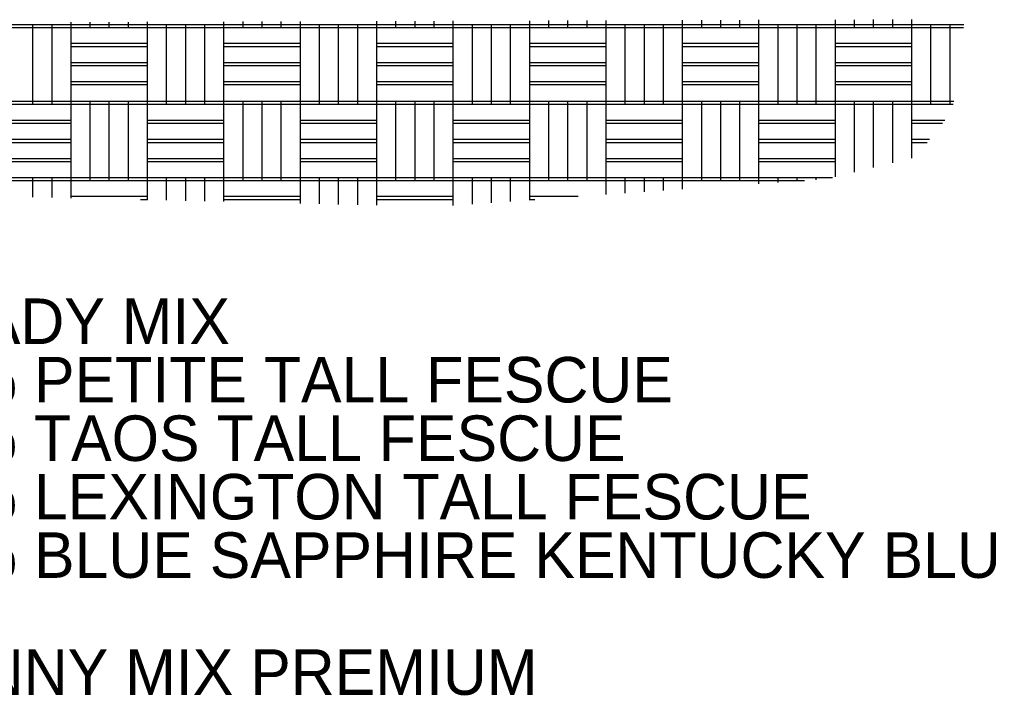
# Model space of a CAD drawing. Extents: x 9966.4 to 10027.9, y 9879.4 to 9942.8.
# Drawn here: x 9984.77 to 10007.1, y 9911.19 to 9926.69 of the extents above; entities that cross this region are included whole.
import ezdxf

# ---------------------------------------------------------------- set-up
doc = ezdxf.new("R2010")
doc.units = 0
for name, color, linetype in [('Default', 7, 'Continuous'), ('G-ANNO-TEXT', 7, 'Continuous'), ('G-DETL-PATT', 7, 'Continuous')]:
    doc.layers.add(name, color=color, linetype=linetype)

msp = doc.modelspace()

# ---------------------------------------------------------------- linework, layer by layer
at = {"layer": 'Default'}
for p, q in [((9998.232, 9926.139), (9996.478, 9926.139)), ((10001.74, 9926.139), (9999.986, 9926.139)), ((10005.248, 9926.139), (10003.494, 9926.139)), ((9996.598, 9922.561), (9996.478, 9922.561))]:
    msp.add_line(p, q, dxfattribs=at)
at = {"layer": 'G-DETL-PATT'}
for p, q in [((9979.4, 9926.578), (10006.438, 9926.578)), ((9985.078, 9924.824), (9985.078, 9926.578)), ((9985.516, 9924.824), (9985.516, 9926.578)), ((9985.954, 9926.578), (9985.954, 9926.631)), ((9985.954, 9926.507), (9985.954, 9926.631)), ((9985.954, 9924.824), (9985.954, 9926.578)), ((9986.393, 9926.578), (9986.393, 9926.632)), ((9986.393, 9926.507), (9986.393, 9926.632)), ((9986.831, 9926.578), (9986.831, 9926.634)), ((9986.831, 9926.507), (9986.831, 9926.634)), ((9987.27, 9926.578), (9987.27, 9926.635)), ((9987.27, 9926.507), (9987.27, 9926.635)), ((9987.708, 9926.578), (9987.708, 9926.637)), ((9987.708, 9926.507), (9987.708, 9926.637)), ((9987.708, 9924.824), (9987.708, 9926.578)), ((9988.147, 9924.824), (9988.147, 9926.578)), ((9988.585, 9924.824), (9988.585, 9926.578)), ((9989.024, 9924.824), (9989.024, 9926.578)), ((9989.462, 9926.578), (9989.462, 9926.642)), ((9989.462, 9926.507), (9989.462, 9926.642)), ((9989.462, 9924.824), (9989.462, 9926.578)), ((9989.901, 9926.578), (9989.901, 9926.644)), ((9989.901, 9926.507), (9989.901, 9926.644)), ((9990.339, 9926.578), (9990.339, 9926.645)), ((9990.339, 9926.507), (9990.339, 9926.645)), ((9990.778, 9926.578), (9990.778, 9926.647)), ((9990.778, 9926.507), (9990.778, 9926.647)), ((9991.216, 9926.578), (9991.216, 9926.648)), ((9991.216, 9926.507), (9991.216, 9926.648)), ((9991.216, 9924.824), (9991.216, 9926.578)), ((9991.655, 9924.824), (9991.655, 9926.578)), ((9992.093, 9924.824), (9992.093, 9926.578)), ((9992.532, 9924.824), (9992.532, 9926.578)), ((9992.97, 9926.578), (9992.97, 9926.654)), ((9992.97, 9926.507), (9992.97, 9926.654)), ((9992.97, 9924.824), (9992.97, 9926.578)), ((9993.409, 9926.578), (9993.409, 9926.655)), ((9993.409, 9926.507), (9993.409, 9926.655)), ((9993.847, 9926.578), (9993.847, 9926.656)), ((9993.847, 9926.507), (9993.847, 9926.656)), ((9994.286, 9926.578), (9994.286, 9926.658)), ((9994.286, 9926.507), (9994.286, 9926.658)), ((9994.724, 9926.578), (9994.724, 9926.659)), ((9994.724, 9926.507), (9994.724, 9926.659)), ((9994.724, 9924.824), (9994.724, 9926.578)), ((9995.163, 9924.824), (9995.163, 9926.578)), ((9995.601, 9924.824), (9995.601, 9926.578)), ((9996.04, 9924.824), (9996.04, 9926.578)), ((9996.478, 9926.578), (9996.478, 9926.665)), ((9996.478, 9926.507), (9996.478, 9926.665)), ((9996.478, 9924.824), (9996.478, 9926.578)), ((9996.917, 9926.578), (9996.917, 9926.667)), ((9996.917, 9926.507), (9996.917, 9926.667)), ((9997.355, 9926.578), (9997.355, 9926.668)), ((9997.355, 9926.507), (9997.355, 9926.668)), ((9997.794, 9926.578), (9997.794, 9926.669)), ((9997.794, 9926.507), (9997.794, 9926.669)), ((9998.232, 9926.578), (9998.232, 9926.671)), ((9998.232, 9926.507), (9998.232, 9926.671)), ((9998.232, 9924.824), (9998.232, 9926.578)), ((9998.671, 9924.824), (9998.671, 9926.578)), ((9999.109, 9924.824), (9999.109, 9926.578)), ((9999.548, 9924.824), (9999.548, 9926.578)), ((9999.986, 9926.578), (9999.986, 9926.676)), ((9999.986, 9926.507), (9999.986, 9926.676)), ((9999.986, 9924.824), (9999.986, 9926.578)), ((10000.425, 9926.578), (10000.425, 9926.678)), ((10000.425, 9926.507), (10000.425, 9926.678)), ((10000.863, 9926.578), (10000.863, 9926.679)), ((10000.863, 9926.507), (10000.863, 9926.679)), ((10001.302, 9926.578), (10001.302, 9926.681)), ((10001.302, 9926.507), (10001.302, 9926.681)), ((10001.74, 9926.578), (10001.74, 9926.682)), ((10001.74, 9926.507), (10001.74, 9926.682)), ((10001.74, 9924.824), (10001.74, 9926.578)), ((10002.179, 9924.824), (10002.179, 9926.578)), ((10002.617, 9924.824), (10002.617, 9926.578)), ((10003.056, 9924.824), (10003.056, 9926.578)), ((10003.494, 9926.578), (10003.494, 9926.688)), ((10003.494, 9926.507), (10003.494, 9926.688)), ((10003.494, 9924.824), (10003.494, 9926.578)), ((10003.933, 9926.578), (10003.933, 9926.689)), ((10003.933, 9926.507), (10003.933, 9926.689)), ((10004.371, 9926.578), (10004.371, 9926.691)), ((10004.371, 9926.507), (10004.371, 9926.691)), ((10004.81, 9926.578), (10004.81, 9926.692)), ((10004.81, 9926.507), (10004.81, 9926.692)), ((10005.248, 9926.578), (10005.248, 9926.694)), ((10005.248, 9926.507), (10005.248, 9926.694)), ((10005.248, 9924.824), (10005.248, 9926.578)), ((10005.687, 9924.824), (10005.687, 9926.578)), ((10006.125, 9924.824), (10006.125, 9926.578)), ((9979.454, 9926.507), (10006.433, 9926.507)), ((9985.078, 9924.753), (9985.078, 9926.507)), ((9985.516, 9924.753), (9985.516, 9926.507)), ((9985.954, 9924.753), (9985.954, 9926.507)), ((9987.708, 9924.753), (9987.708, 9926.507)), ((9988.147, 9924.753), (9988.147, 9926.507)), ((9988.585, 9924.753), (9988.585, 9926.507)), ((9989.024, 9924.753), (9989.024, 9926.507)), ((9989.462, 9924.753), (9989.462, 9926.507)), ((9991.216, 9924.753), (9991.216, 9926.507)), ((9991.655, 9924.753), (9991.655, 9926.507)), ((9992.093, 9924.753), (9992.093, 9926.507)), ((9992.532, 9924.753), (9992.532, 9926.507)), ((9992.97, 9924.753), (9992.97, 9926.507)), ((9994.724, 9924.753), (9994.724, 9926.507)), ((9995.163, 9924.753), (9995.163, 9926.507)), ((9995.601, 9924.753), (9995.601, 9926.507)), ((9996.04, 9924.753), (9996.04, 9926.507)), ((9996.478, 9924.753), (9996.478, 9926.507)), ((9998.232, 9924.753), (9998.232, 9926.507)), ((9998.671, 9924.753), (9998.671, 9926.507)), ((9999.109, 9924.753), (9999.109, 9926.507)), ((9999.548, 9924.753), (9999.548, 9926.507)), ((9999.986, 9924.753), (9999.986, 9926.507)), ((10001.74, 9924.753), (10001.74, 9926.507)), ((10002.179, 9924.753), (10002.179, 9926.507)), ((10002.617, 9924.753), (10002.617, 9926.507)), ((10003.056, 9924.753), (10003.056, 9926.507)), ((10003.494, 9924.753), (10003.494, 9926.507)), ((10005.248, 9924.753), (10005.248, 9926.507)), ((10005.687, 9924.753), (10005.687, 9926.507)), ((10006.125, 9924.753), (10006.125, 9926.507)), ((9987.708, 9926.139), (9985.954, 9926.139)), ((9991.216, 9926.139), (9989.462, 9926.139)), ((9994.724, 9926.139), (9992.97, 9926.139)), ((9987.708, 9926.069), (9985.954, 9926.069)), ((9991.216, 9926.069), (9989.462, 9926.069)), ((9994.724, 9926.069), (9992.97, 9926.069)), ((9998.232, 9926.069), (9996.478, 9926.069)), ((10001.74, 9926.069), (9999.986, 9926.069)), ((10005.248, 9926.069), (10003.494, 9926.069)), ((9987.708, 9925.701), (9985.954, 9925.701)), ((9987.708, 9925.63), (9985.954, 9925.63)), ((9991.216, 9925.701), (9989.462, 9925.701)), ((9991.216, 9925.63), (9989.462, 9925.63)), ((9994.724, 9925.701), (9992.97, 9925.701)), ((9994.724, 9925.63), (9992.97, 9925.63)), ((9998.232, 9925.701), (9996.478, 9925.701)), ((9998.232, 9925.63), (9996.478, 9925.63)), ((10001.74, 9925.701), (9999.986, 9925.701)), ((10001.74, 9925.63), (9999.986, 9925.63)), ((10005.248, 9925.701), (10003.494, 9925.701)), ((10005.248, 9925.63), (10003.494, 9925.63)), ((9987.708, 9925.262), (9985.954, 9925.262)), ((9987.708, 9925.192), (9985.954, 9925.192)), ((9991.216, 9925.262), (9989.462, 9925.262)), ((9991.216, 9925.192), (9989.462, 9925.192)), ((9994.724, 9925.262), (9992.97, 9925.262)), ((9994.724, 9925.192), (9992.97, 9925.192)), ((9998.232, 9925.262), (9996.478, 9925.262)), ((9998.232, 9925.192), (9996.478, 9925.192)), ((10001.74, 9925.262), (9999.986, 9925.262)), ((10001.74, 9925.192), (9999.986, 9925.192)), ((10005.248, 9925.262), (10003.494, 9925.262)), ((10005.248, 9925.192), (10003.494, 9925.192)), ((9980.74, 9924.824), (10006.208, 9924.824)), ((9980.794, 9924.753), (10006.196, 9924.753)), ((9984.201, 9924.824), (9985.954, 9924.824)), ((9984.201, 9924.753), (9985.954, 9924.753)), ((9985.954, 9923.07), (9985.954, 9924.824)), ((9985.954, 9922.999), (9985.954, 9924.753)), ((9986.393, 9923.07), (9986.393, 9924.824)), ((9986.393, 9922.999), (9986.393, 9924.753)), ((9986.831, 9923.07), (9986.831, 9924.824)), ((9986.831, 9922.999), (9986.831, 9924.753)), ((9987.27, 9923.07), (9987.27, 9924.824)), ((9987.27, 9922.999), (9987.27, 9924.753)), ((9987.708, 9923.07), (9987.708, 9924.824)), ((9987.708, 9924.824), (9989.462, 9924.824)), ((9987.708, 9922.999), (9987.708, 9924.753)), ((9987.708, 9924.753), (9989.462, 9924.753)), ((9989.462, 9923.07), (9989.462, 9924.824)), ((9989.462, 9922.999), (9989.462, 9924.753)), ((9989.901, 9923.07), (9989.901, 9924.824)), ((9989.901, 9922.999), (9989.901, 9924.753)), ((9990.339, 9923.07), (9990.339, 9924.824)), ((9990.339, 9922.999), (9990.339, 9924.753)), ((9990.778, 9923.07), (9990.778, 9924.824)), ((9990.778, 9922.999), (9990.778, 9924.753)), ((9991.216, 9923.07), (9991.216, 9924.824)), ((9991.216, 9924.824), (9992.97, 9924.824)), ((9991.216, 9922.999), (9991.216, 9924.753)), ((9991.216, 9924.753), (9992.97, 9924.753)), ((9992.97, 9923.07), (9992.97, 9924.824)), ((9992.97, 9922.999), (9992.97, 9924.753)), ((9993.409, 9923.07), (9993.409, 9924.824)), ((9993.409, 9922.999), (9993.409, 9924.753)), ((9993.847, 9923.07), (9993.847, 9924.824)), ((9993.847, 9922.999), (9993.847, 9924.753)), ((9994.286, 9923.07), (9994.286, 9924.824)), ((9994.286, 9922.999), (9994.286, 9924.753)), ((9994.724, 9923.07), (9994.724, 9924.824)), ((9994.724, 9924.824), (9996.478, 9924.824)), ((9994.724, 9922.999), (9994.724, 9924.753)), ((9994.724, 9924.753), (9996.478, 9924.753)), ((9996.478, 9923.07), (9996.478, 9924.824)), ((9996.478, 9922.999), (9996.478, 9924.753)), ((9996.917, 9923.07), (9996.917, 9924.824)), ((9996.917, 9922.999), (9996.917, 9924.753)), ((9997.355, 9923.07), (9997.355, 9924.824)), ((9997.355, 9922.999), (9997.355, 9924.753)), ((9997.794, 9923.07), (9997.794, 9924.824)), ((9997.794, 9922.999), (9997.794, 9924.753)), ((9998.232, 9923.07), (9998.232, 9924.824)), ((9998.232, 9924.824), (9999.986, 9924.824)), ((9998.232, 9922.999), (9998.232, 9924.753)), ((9998.232, 9924.753), (9999.986, 9924.753)), ((9999.986, 9923.07), (9999.986, 9924.824)), ((9999.986, 9922.999), (9999.986, 9924.753)), ((10000.425, 9923.07), (10000.425, 9924.824)), ((10000.425, 9922.999), (10000.425, 9924.753)), ((10000.863, 9923.07), (10000.863, 9924.824)), ((10000.863, 9922.999), (10000.863, 9924.753)), ((10001.302, 9923.07), (10001.302, 9924.824)), ((10001.302, 9922.999), (10001.302, 9924.753)), ((10001.74, 9923.07), (10001.74, 9924.824)), ((10001.74, 9924.824), (10003.494, 9924.824)), ((10001.74, 9922.999), (10001.74, 9924.753)), ((10001.74, 9924.753), (10003.494, 9924.753)), ((10003.494, 9923.086), (10003.494, 9924.824)), ((10003.494, 9923.086), (10003.494, 9924.753)), ((10003.933, 9923.192), (10003.933, 9924.824)), ((10003.933, 9923.192), (10003.933, 9924.753)), ((10004.371, 9923.298), (10004.371, 9924.824)), ((10004.371, 9923.298), (10004.371, 9924.753)), ((10004.81, 9923.404), (10004.81, 9924.824)), ((10004.81, 9923.404), (10004.81, 9924.753)), ((10005.248, 9923.51), (10005.248, 9924.824)), ((10005.248, 9924.824), (10006.208, 9924.824)), ((10005.248, 9923.51), (10005.248, 9924.753)), ((10005.248, 9924.753), (10006.196, 9924.753)), ((9984.201, 9924.385), (9985.954, 9924.385)), ((9984.201, 9924.315), (9985.954, 9924.315)), ((9987.708, 9924.385), (9989.462, 9924.385)), ((9987.708, 9924.315), (9989.462, 9924.315)), ((9991.216, 9924.385), (9992.97, 9924.385)), ((9991.216, 9924.315), (9992.97, 9924.315)), ((9994.724, 9924.385), (9996.478, 9924.385)), ((9994.724, 9924.315), (9996.478, 9924.315)), ((9998.232, 9924.385), (9999.986, 9924.385)), ((9998.232, 9924.315), (9999.986, 9924.315)), ((10001.74, 9924.385), (10003.494, 9924.385)), ((10001.74, 9924.315), (10003.494, 9924.315)), ((10005.248, 9924.385), (10006.007, 9924.385)), ((10005.248, 9924.315), (10005.95, 9924.315)), ((9984.201, 9923.947), (9985.954, 9923.947)), ((9984.201, 9923.876), (9985.954, 9923.876)), ((9987.708, 9923.947), (9989.462, 9923.947)), ((9987.708, 9923.876), (9989.462, 9923.876)), ((9991.216, 9923.947), (9992.97, 9923.947)), ((9991.216, 9923.876), (9992.97, 9923.876)), ((9994.724, 9923.947), (9996.478, 9923.947)), ((9994.724, 9923.876), (9996.478, 9923.876)), ((9998.232, 9923.947), (9999.986, 9923.947)), ((9998.232, 9923.876), (9999.986, 9923.876)), ((10001.74, 9923.947), (10003.494, 9923.947)), ((10001.74, 9923.876), (10003.494, 9923.876)), ((10005.248, 9923.947), (10005.656, 9923.947)), ((10005.248, 9923.876), (10005.6, 9923.876)), ((9984.201, 9923.508), (9985.954, 9923.508)), ((9984.201, 9923.438), (9985.954, 9923.438)), ((9987.708, 9923.508), (9989.462, 9923.508)), ((9987.708, 9923.438), (9989.462, 9923.438)), ((9991.216, 9923.508), (9992.97, 9923.508)), ((9991.216, 9923.438), (9992.97, 9923.438)), ((9994.724, 9923.508), (9996.478, 9923.508)), ((9994.724, 9923.438), (9996.478, 9923.438)), ((9998.232, 9923.508), (9999.986, 9923.508)), ((9998.232, 9923.438), (9999.986, 9923.438)), ((10001.74, 9923.508), (10003.494, 9923.508)), ((10001.74, 9923.438), (10003.494, 9923.438)), ((9982.08, 9923.07), (10003.425, 9923.07)), ((9982.134, 9922.999), (10002.781, 9922.999)), ((9985.078, 9922.619), (9985.078, 9923.07)), ((9985.078, 9922.619), (9985.078, 9922.999)), ((9985.516, 9922.609), (9985.516, 9923.07)), ((9985.516, 9922.609), (9985.516, 9922.999)), ((9985.954, 9922.598), (9985.954, 9923.07)), ((9985.954, 9922.598), (9985.954, 9922.999)), ((9987.708, 9922.557), (9987.708, 9923.07)), ((9987.708, 9922.557), (9987.708, 9922.999)), ((9988.147, 9922.547), (9988.147, 9923.07)), ((9988.147, 9922.547), (9988.147, 9922.999)), ((9988.585, 9922.536), (9988.585, 9923.07)), ((9988.585, 9922.536), (9988.585, 9922.999)), ((9989.024, 9922.526), (9989.024, 9923.07)), ((9989.024, 9922.526), (9989.024, 9922.999)), ((9989.462, 9922.516), (9989.462, 9923.07)), ((9989.462, 9922.516), (9989.462, 9922.999)), ((9991.216, 9922.474), (9991.216, 9923.07)), ((9991.216, 9922.474), (9991.216, 9922.999)), ((9991.655, 9922.464), (9991.655, 9923.07)), ((9991.655, 9922.464), (9991.655, 9922.999)), ((9992.093, 9922.454), (9992.093, 9923.07)), ((9992.093, 9922.454), (9992.093, 9922.999)), ((9992.532, 9922.443), (9992.532, 9923.07)), ((9992.532, 9922.443), (9992.532, 9922.999)), ((9992.97, 9922.433), (9992.97, 9923.07)), ((9992.97, 9922.433), (9992.97, 9922.999)), ((9994.724, 9922.428), (9994.724, 9923.07)), ((9994.724, 9922.428), (9994.724, 9922.999)), ((9995.163, 9922.459), (9995.163, 9923.07)), ((9995.163, 9922.459), (9995.163, 9922.999)), ((9995.601, 9922.49), (9995.601, 9923.07)), ((9995.601, 9922.49), (9995.601, 9922.999)), ((9996.04, 9922.521), (9996.04, 9923.07)), ((9996.04, 9922.521), (9996.04, 9922.999)), ((9996.478, 9922.552), (9996.478, 9923.07)), ((9996.478, 9922.552), (9996.478, 9922.999)), ((9998.232, 9922.677), (9998.232, 9923.07)), ((9998.232, 9922.677), (9998.232, 9922.999)), ((9998.671, 9922.708), (9998.671, 9923.07)), ((9998.671, 9922.708), (9998.671, 9922.999)), ((9999.109, 9922.739), (9999.109, 9923.07)), ((9999.109, 9922.739), (9999.109, 9922.999)), ((9999.548, 9922.77), (9999.548, 9923.07)), ((9999.548, 9922.77), (9999.548, 9922.999)), ((9999.986, 9922.801), (9999.986, 9923.07)), ((9999.986, 9922.801), (9999.986, 9922.999)), ((10001.74, 9922.925), (10001.74, 9923.07)), ((10001.74, 9922.925), (10001.74, 9922.999)), ((10002.179, 9922.957), (10002.179, 9923.07)), ((10002.179, 9922.957), (10002.179, 9922.999)), ((10002.617, 9922.988), (10002.617, 9923.07)), ((10002.617, 9922.988), (10002.617, 9922.999)), ((10003.056, 9923.019), (10003.056, 9923.07)), ((9987.708, 9922.631), (9985.954, 9922.631)), ((9987.708, 9922.561), (9987.545, 9922.561)), ((9991.216, 9922.631), (9989.462, 9922.631)), ((9991.216, 9922.561), (9989.462, 9922.561)), ((9994.724, 9922.631), (9992.97, 9922.631)), ((9994.724, 9922.561), (9992.97, 9922.561)), ((9997.591, 9922.631), (9996.478, 9922.631))]:
    msp.add_line(p, q, dxfattribs=at)

# ---------------------------------------------------------------- texts
at = {"layer": 'G-ANNO-TEXT'}
for s, p in [('SHADY MIX', (9981.92, 9919.252)), ('30% PETITE TALL FESCUE', (9981.92, 9917.911)), ('30% TAOS TALL FESCUE', (9981.92, 9916.57)), ('30% LEXINGTON TALL FESCUE', (9981.92, 9915.229)), ('10% BLUE SAPPHIRE KENTUCKY BLUEGRASS', (9981.92, 9913.889)), ('SUNNY MIX PREMIUM', (9981.92, 9911.207))]:
    msp.add_text(s, height=1.044, dxfattribs=at).set_placement(p)

doc.saveas('drawing.dxf')
